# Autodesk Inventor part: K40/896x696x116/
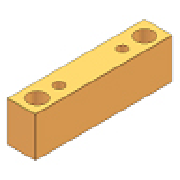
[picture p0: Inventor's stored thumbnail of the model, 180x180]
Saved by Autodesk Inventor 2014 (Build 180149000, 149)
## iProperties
IsCustomPart: 1
Created: 2009-11
Part Number: K40/896x696x116/
Material: DIN 1.1730
Description: Spacer Block
Document SubType Name: Modeling
Designer: gaom
Standard Revision: 1
Manufacturer: HASCO
Language: en-US
Size Designation: 896x696x116/
Categories: <MemberInstance><Categories><Category DisplayName="Mold" InternalName="349578f2-f4d4-4954-8c09-8e99297a61c0" Mnemonic="MOLD"><Category DisplayName="Mold Plates"
Density: 7.82 g/cm^3
Appearance: Orange (Pale)
Author: gaom
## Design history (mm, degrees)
sketch "Sketch1"
  geometry: L1 (-264, 448)-(-348, 448); L2 (-348, 448)-(-348, -448); L3 (-348, -448)-(-264, -448); L4 (-264, -448)-(-264, 448); L5 (348, 448)-(348, -448); L6 (264, -448)-(264, 448); L7 (264, 448)-(348, 448); L8 (264, -448)-(348, -448); 7 further points
  constraints: 16 end point, 3 parallel, 2 horizontal alignment, 2 midpoint, 2 perpendicular, 1 horizontal, 1 vertical
  dimensions: "d85" = 896 distance between parallel lines of L3 L1 (= L); "d86" = 84 distance between parallel lines of L4 L2 (= W_); "d88" = 84 distance between parallel lines of L5 L6 (= W_); "d89" = 348 distance from line of point (0, 0) L2 (= 0.5 x M_W); "d93" = 896 distance between parallel lines of L8 L7 (= L); "d94" = 348 distance from line of point (0, 0) L5 (= 0.5 x M_W); "d98" = 337 vertical distance of point (-296, 337) point (0, 0) (= 0.5 x S1_L); "d100" = 296 horizontal distance of point (-296, 337) point (0, 0) (= 0.5 x S1_W); "d101" = 296 horizontal distance of point (296, 337) point (0, 0) (= 0.5 x S1_W); "d102" = 337 vertical distance of point (0, 0) point (296, 337) (= 0.5 x S1_L); "d103" = 296 horizontal distance of point (-296, 396) point (0, 0) (= 0.5 x LS_W); "d105" = 396 vertical distance of point (-296, 396) point (0, 0) (= 0.5 x LS_L); "d106" = 296 horizontal distance of point (0, 0) point (296, 396) (= 0.5 x LS_W); "d107" = 396 vertical distance of point (296, 396) point (0, 0) (= 0.5 x LS_L)
extrude "Extrusion1" new body sketch "Sketch1" distance "d20" = 116 (= H_); taper "d30" = 0 deg
extrude "Extrusion2" join sketch "Sketch1" distance "d95" = 116 (= H_); taper "d96" = 0 deg
body "Solid1"
hole "Hole1" sketch "Sketch1" diameter "d129" = 22 (= S1_d1); stored, may be unused: countersink angle "d133" = 90 deg, drill point angle "d135" = 0 deg; dims "d130" = 6, "d131" = 4, "d132" = 2, "d134" = 116 (= H_)
pattern_linear "Rectangular Pattern1" dims "d156" = 674 (computed from S1_L, Ns)
hole "Hole2" sketch "Sketch1" diameter "d108" = 54 (= LS_d); stored, may be unused: countersink angle "d112" = 90 deg, drill point angle "d114" = 0 deg; dims "d109" = 6, "d110" = 4, "d111" = 2, "d113" = 116 (= H_)
pattern_linear "Rectangular Pattern2" dims "d138" = 792 (computed from LS_L, Nl)
hole "Hole3" sketch "Sketch1" diameter "d122" = 22 (= S1_d1); stored, may be unused: countersink angle "d126" = 90 deg, drill point angle "d128" = 0 deg; dims "d123" = 6, "d124" = 4, "d125" = 2, "d127" = 116 (= H_)
pattern_linear "Rectangular Pattern3" dims "d153" = 674 (computed from S1_L, Ns)
hole "Hole4" sketch "Sketch1" diameter "d115" = 54 (= LS_d); stored, may be unused: countersink angle "d119" = 90 deg, drill point angle "d121" = 0 deg; dims "d116" = 6, "d117" = 4, "d118" = 2, "d120" = 116 (= H_)
pattern_linear "Rectangular Pattern4" dims "d150" = 792 (computed from LS_L, Nl)
chamfer "Chamfer1" distance "d82" = 0.5; stored, may be unused: second distance "d83" = 2, angle "d84" = 45 deg
chamfer "Chamfer2" distance "d157" = 0.5; stored, may be unused: second distance "d158" = 2, angle "d159" = 45 deg
workplane "Work Plane1"
workplane "Work Plane2"
other parameters: "L" = 896 [user parameter; used in 2 equation terms], "W_" = 84 [user parameter; used in 2 equation terms], "H_" = 116 [user parameter; used in 7 equation terms], "M_W" = 696 [user parameter; used in 2 equation terms], "S1_L" = 674 [user parameter; used in 4 equation terms], "S1_W" = 592 [user parameter; used in 2 equation terms], "S1_d1" = 22 [user parameter; used in 2 equation terms], "LS_L" = 792 [user parameter; used in 4 equation terms], "LS_W" = 592 [user parameter; used in 2 equation terms], "LS_d" = 54 [user parameter; used in 2 equation terms], "d161" = 0, "d162" = 116 (= H_)
